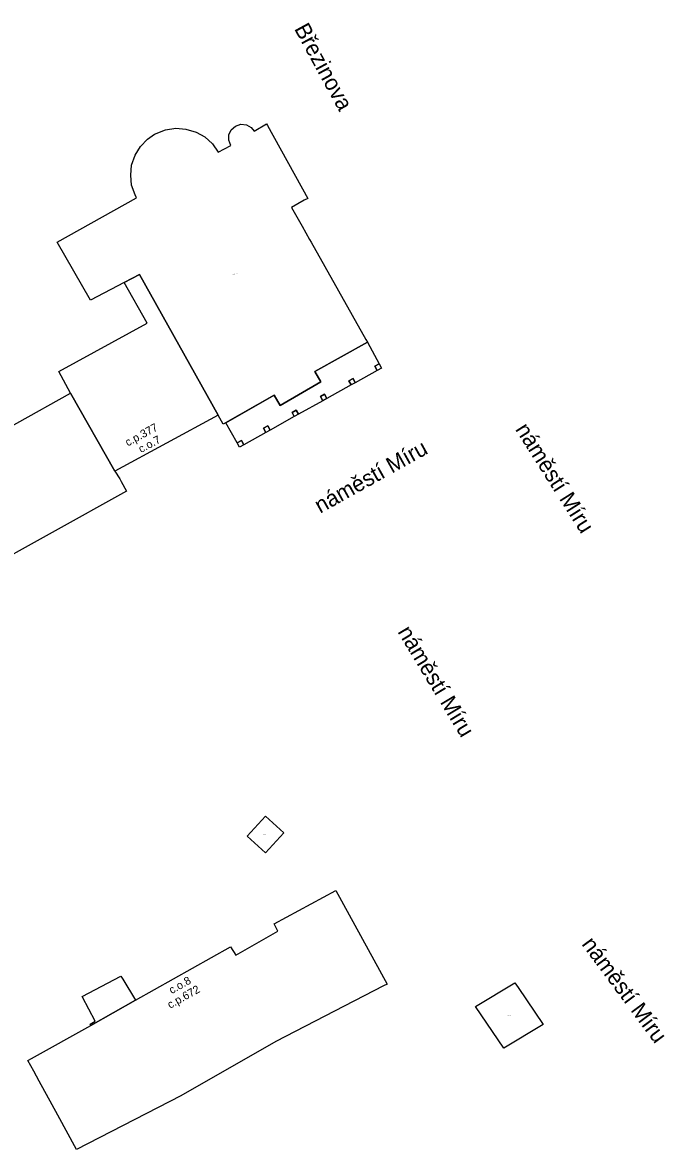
# Model space of a CAD drawing. Extents: x -600391 to -599491, y -1160176 to -1159402.
# Drawn here: x -600035.1 to -599954.9, y -1159820.6 to -1159679.8 of the extents above; entities that cross this region are included whole.
import ezdxf

# ---------------------------------------------------------------- set-up
doc = ezdxf.new("R2010")
doc.units = 0
for name, color, linetype in [('Level 10', 7, 'Continuous'), ('Level 11', 7, 'Continuous'), ('Level 12', 7, 'Continuous'), ('Level 24', 7, 'Continuous'), ('Level 25', 7, 'Continuous'), ('Level 61', 7, 'Continuous'), ('Level 62', 7, 'Continuous')]:
    doc.layers.add(name, color=color, linetype=linetype)

msp = doc.modelspace()

# ---------------------------------------------------------------- linework, layer by layer
at = {"layer": 'Level 61'}
for points in [[(-600018.61, -1159693.77), (-600017.24, -1159693.22)], [(-600017.24, -1159693.22), (-600015.96, -1159693.03)], [(-600015.96, -1159693.03), (-600014.69, -1159693.13)], [(-600014.69, -1159693.13), (-600013.44, -1159693.51)], [(-600013.44, -1159693.51), (-600012.35, -1159694.12)], [(-600009.32, -1159693.84), (-600009.04, -1159693.22)], [(-600009.04, -1159693.22), (-600008.52, -1159692.78)], [(-600008.52, -1159692.78), (-600007.84, -1159692.54)], [(-600007.84, -1159692.54), (-600007.14, -1159692.62)], [(-600007.14, -1159692.62), (-600006.54, -1159692.96)], [(-600006.54, -1159692.96), (-600006.18, -1159693.38)], [(-600006.18, -1159693.38), (-600004.65, -1159692.47)], [(-600004.65, -1159692.47), (-600004.52, -1159692.71)], [(-600004.52, -1159692.71), (-599999.49, -1159701.8)], [(-600020.37, -1159695.31), (-600019.5, -1159694.38)], [(-600019.5, -1159694.38), (-600018.61, -1159693.77)], [(-600012.35, -1159694.12), (-600011.38, -1159695)], [(-600011.38, -1159695), (-600010.66, -1159696.02)], [(-600009.35, -1159694.53), (-600009.32, -1159693.84)], [(-600009.1, -1159695.2), (-600009.35, -1159694.53)], [(-600021.48, -1159697.64), (-600021.05, -1159696.4)], [(-600021.05, -1159696.4), (-600020.37, -1159695.31)], [(-600010.66, -1159696.02), (-600009.1, -1159695.2)], [(-600021.6, -1159698.88), (-600021.48, -1159697.64)], [(-600021.48, -1159700.14), (-600021.6, -1159698.88)], [(-600021.04, -1159701.36), (-600021.48, -1159700.14)], [(-600030.77, -1159707.26), (-600020.86, -1159701.72)], [(-600020.86, -1159701.72), (-600021.04, -1159701.36)], [(-599999.92, -1159702.04), (-600001.52, -1159702.92)], [(-599999.49, -1159701.8), (-599999.92, -1159702.04)], [(-600001.52, -1159702.92), (-600000.19, -1159705.25)], [(-600000.19, -1159705.25), (-599999.27, -1159706.95)], [(-600026.6, -1159714.52), (-600030.77, -1159707.26)], [(-599999.27, -1159706.95), (-599999.05, -1159707.28)], [(-599999.05, -1159707.28), (-599992.21, -1159719.41)], [(-600020.51, -1159711.3), (-600022.4, -1159712.29)], [(-600022.4, -1159712.29), (-600020.51, -1159711.3)], [(-600010.67, -1159728.89), (-600020.51, -1159711.3)], [(-600020.51, -1159711.3), (-600010.67, -1159728.89)], [(-600022.4, -1159712.29), (-600026.6, -1159714.52)], [(-600019.53, -1159717.38), (-600022.4, -1159712.29)], [(-600030.58, -1159723.41), (-600019.53, -1159717.38)], [(-599998.6, -1159723.43), (-599992, -1159719.77)], [(-599992, -1159719.77), (-599998.6, -1159723.43)], [(-599992.21, -1159719.41), (-599992, -1159719.77)], [(-599992, -1159719.77), (-599990.56, -1159722.46)], [(-599991.1, -1159722.76), (-599990.56, -1159722.46)], [(-599990.56, -1159722.46), (-599991.1, -1159722.76)], [(-599990.8, -1159723.28), (-599991.1, -1159722.76)], [(-599991.1, -1159722.76), (-599990.8, -1159723.28)], [(-599990.28, -1159722.99), (-599990.8, -1159723.28)], [(-599990.56, -1159722.46), (-599990.28, -1159722.99)], [(-600029.11, -1159726.12), (-600030.58, -1159723.41)], [(-599997.85, -1159724.73), (-599998.6, -1159723.43)], [(-599998.6, -1159723.43), (-599997.85, -1159724.73)], [(-599994.36, -1159724.58), (-599993.83, -1159724.28)], [(-599993.83, -1159724.28), (-599994.36, -1159724.58)], [(-599994.07, -1159725.1), (-599994.36, -1159724.58)], [(-599994.36, -1159724.58), (-599994.07, -1159725.1)], [(-599993.83, -1159724.28), (-599993.54, -1159724.82)], [(-599993.54, -1159724.82), (-599993.83, -1159724.28)], [(-599990.8, -1159723.28), (-599993.54, -1159724.82)], [(-600002.93, -1159727.66), (-599997.85, -1159724.73)], [(-599997.85, -1159724.73), (-600002.93, -1159727.66)], [(-599994.07, -1159725.1), (-599997.08, -1159726.8)], [(-599993.54, -1159724.82), (-599994.07, -1159725.1)], [(-600035.83, -1159729.89), (-600029.11, -1159726.12)], [(-600023.56, -1159735.86), (-600029.11, -1159726.12)], [(-600029.11, -1159726.12), (-600023.56, -1159735.86)], [(-600003.68, -1159726.39), (-600010.03, -1159730)], [(-600009.73, -1159729.83), (-600003.68, -1159726.39)], [(-600003.68, -1159726.39), (-600002.93, -1159727.66)], [(-600002.93, -1159727.66), (-600003.68, -1159726.39)], [(-599997.61, -1159727.08), (-600000.63, -1159728.77)], [(-599997.9, -1159726.55), (-599997.38, -1159726.26)], [(-599997.38, -1159726.26), (-599997.9, -1159726.55)], [(-599997.61, -1159727.08), (-599997.9, -1159726.55)], [(-599997.9, -1159726.55), (-599997.61, -1159727.08)], [(-599997.08, -1159726.8), (-599997.61, -1159727.08)], [(-599997.38, -1159726.26), (-599997.08, -1159726.8)], [(-599997.08, -1159726.8), (-599997.38, -1159726.26)], [(-600001.45, -1159728.53), (-600000.93, -1159728.24)], [(-600000.93, -1159728.24), (-600001.45, -1159728.53)], [(-600001.16, -1159729.05), (-600001.45, -1159728.53)], [(-600001.45, -1159728.53), (-600001.16, -1159729.05)], [(-600000.63, -1159728.77), (-600001.16, -1159729.05)], [(-600000.93, -1159728.24), (-600000.63, -1159728.77)], [(-600000.63, -1159728.77), (-600000.93, -1159728.24)], [(-600010.67, -1159728.89), (-600023.56, -1159735.86)], [(-600010.03, -1159730), (-600010.67, -1159728.89)], [(-600008.28, -1159732.34), (-600009.73, -1159729.83)], [(-600005, -1159730.51), (-600004.47, -1159730.21)], [(-600004.47, -1159730.21), (-600005, -1159730.51)], [(-600004.47, -1159730.21), (-600004.17, -1159730.75)], [(-600004.17, -1159730.75), (-600004.47, -1159730.21)], [(-600001.16, -1159729.05), (-600004.17, -1159730.75)], [(-600004.71, -1159731.03), (-600007.46, -1159732.58)], [(-600004.71, -1159731.03), (-600005, -1159730.51)], [(-600005, -1159730.51), (-600004.71, -1159731.03)], [(-600004.17, -1159730.75), (-600004.71, -1159731.03)], [(-600008.28, -1159732.34), (-600007.76, -1159732.04)], [(-600007.76, -1159732.04), (-600008.28, -1159732.34)], [(-600007.99, -1159732.86), (-600008.28, -1159732.34)], [(-600007.46, -1159732.58), (-600007.99, -1159732.86)], [(-600007.76, -1159732.04), (-600007.46, -1159732.58)], [(-600007.46, -1159732.58), (-600007.76, -1159732.04)], [(-600023.56, -1159735.86), (-600022.96, -1159736.85)], [(-600022.96, -1159736.85), (-600022.79, -1159737.15)], [(-600022.79, -1159737.15), (-600022.11, -1159738.38)], [(-600022.11, -1159738.38), (-600040.75, -1159748.71)], [(-600007.05, -1159781.48), (-600004.78, -1159778.98)], [(-600004.78, -1159778.98), (-600002.49, -1159781.04)], [(-600004.76, -1159783.54), (-600007.05, -1159781.48)], [(-600002.49, -1159781.04), (-600004.76, -1159783.54)], [(-600003.69, -1159792.44), (-599995.99, -1159788.26)], [(-599995.99, -1159788.26), (-599989.55, -1159799.94)], [(-600008.47, -1159796.34), (-600003.23, -1159793.33)], [(-600003.23, -1159793.33), (-600003.69, -1159792.44)], [(-600020.99, -1159801.96), (-600009.14, -1159795.29)], [(-600009.14, -1159795.29), (-600008.47, -1159796.34)], [(-600027.66, -1159801.51), (-600022.81, -1159798.97)], [(-600022.81, -1159798.97), (-600022.59, -1159799.32)], [(-600022.59, -1159799.32), (-600020.99, -1159801.96)], [(-599990.01, -1159800.18), (-600003.47, -1159807.14)], [(-599989.55, -1159799.94), (-599990.01, -1159800.18)], [(-599978.52, -1159802.75), (-599973.61, -1159799.78)], [(-599973.61, -1159799.78), (-599973.2, -1159800.38)], [(-599973.2, -1159800.38), (-599970.07, -1159805)], [(-600027.61, -1159801.6), (-600027.66, -1159801.51)], [(-600026.03, -1159804.58), (-600027.61, -1159801.6)], [(-600026.56, -1159805.11), (-600020.99, -1159801.96)], [(-600020.99, -1159801.96), (-600026.56, -1159805.11)], [(-599975, -1159807.96), (-599978.52, -1159802.75)], [(-600026.66, -1159804.94), (-600026.03, -1159804.58)], [(-600033.98, -1159809.23), (-600026.56, -1159805.11)], [(-600026.56, -1159805.11), (-600026.66, -1159804.94)], [(-599970.07, -1159805), (-599975, -1159807.96)], [(-600003.47, -1159807.14), (-600015.35, -1159813.93)], [(-600034.43, -1159809.48), (-600033.98, -1159809.23)], [(-600033.7, -1159810.82), (-600034.43, -1159809.48)], [(-600033.01, -1159812.09), (-600033.7, -1159810.82)], [(-600031.42, -1159815.02), (-600033.01, -1159812.09)], [(-600015.35, -1159813.93), (-600028.35, -1159820.61)], [(-600030.71, -1159816.31), (-600031.42, -1159815.02)], [(-600028.35, -1159820.61), (-600030.71, -1159816.31)]]:
    msp.add_lwpolyline(points, dxfattribs=at)
at = {"layer": 'Level 62'}
for points in [[(-599999.27, -1159706.95), (-599999.05, -1159707.28), (-599992.21, -1159719.41), (-599992, -1159719.77), (-599998.6, -1159723.43), (-599997.85, -1159724.73), (-600002.93, -1159727.66), (-600003.68, -1159726.39), (-600010.03, -1159730), (-600010.67, -1159728.89), (-600020.51, -1159711.3), (-600022.4, -1159712.29), (-600026.6, -1159714.52), (-600030.77, -1159707.26), (-600020.86, -1159701.72), (-600021.04, -1159701.36), (-600021.48, -1159700.14), (-600021.6, -1159698.88), (-600021.48, -1159697.64), (-600021.05, -1159696.4), (-600020.37, -1159695.31), (-600019.5, -1159694.38), (-600018.61, -1159693.77), (-600017.24, -1159693.22), (-600015.96, -1159693.03), (-600014.69, -1159693.13), (-600013.44, -1159693.51), (-600012.35, -1159694.12), (-600011.38, -1159695), (-600010.66, -1159696.02), (-600009.1, -1159695.2), (-600009.35, -1159694.53), (-600009.32, -1159693.84), (-600009.04, -1159693.22), (-600008.52, -1159692.78), (-600007.84, -1159692.54), (-600007.14, -1159692.62), (-600006.54, -1159692.96), (-600006.18, -1159693.38), (-600004.65, -1159692.47), (-600004.52, -1159692.71), (-599999.49, -1159701.8), (-599999.92, -1159702.04), (-600001.52, -1159702.92), (-600000.19, -1159705.25), (-599999.27, -1159706.95)], [(-600029.11, -1159726.12), (-600030.58, -1159723.41), (-600019.53, -1159717.38), (-600022.4, -1159712.29), (-600020.51, -1159711.3), (-600010.67, -1159728.89), (-600023.56, -1159735.86), (-600029.11, -1159726.12)], [(-600007.46, -1159732.58), (-600007.76, -1159732.04), (-600008.28, -1159732.34), (-600009.73, -1159729.83), (-600003.68, -1159726.39), (-600002.93, -1159727.66), (-599997.85, -1159724.73), (-599998.6, -1159723.43), (-599992, -1159719.77), (-599990.56, -1159722.46), (-599991.1, -1159722.76), (-599990.8, -1159723.28), (-599993.54, -1159724.82), (-599993.83, -1159724.28), (-599994.36, -1159724.58), (-599994.07, -1159725.1), (-599997.08, -1159726.8), (-599997.38, -1159726.26), (-599997.9, -1159726.55), (-599997.61, -1159727.08), (-600000.63, -1159728.77), (-600000.93, -1159728.24), (-600001.45, -1159728.53), (-600001.16, -1159729.05), (-600004.17, -1159730.75), (-600004.47, -1159730.21), (-600005, -1159730.51), (-600004.71, -1159731.03), (-600007.46, -1159732.58)], [(-599990.56, -1159722.46), (-599990.28, -1159722.99), (-599990.8, -1159723.28), (-599991.1, -1159722.76), (-599990.56, -1159722.46)], [(-599994.07, -1159725.1), (-599994.36, -1159724.58), (-599993.83, -1159724.28), (-599993.54, -1159724.82), (-599994.07, -1159725.1)], [(-600029.11, -1159726.12), (-600023.56, -1159735.86), (-600022.96, -1159736.85), (-600022.79, -1159737.15), (-600022.11, -1159738.38), (-600040.75, -1159748.71), (-600041.39, -1159749.06), (-600044.45, -1159750.75), (-600045.04, -1159751.07), (-600045.74, -1159751.46), (-600063.64, -1159761.34), (-600070.35, -1159749.14), (-600052.61, -1159739.29), (-600051.53, -1159738.69), (-600047.82, -1159736.59), (-600042.29, -1159733.51), (-600037.91, -1159731.05), (-600035.83, -1159729.89), (-600029.11, -1159726.12)], [(-599997.08, -1159726.8), (-599997.61, -1159727.08), (-599997.9, -1159726.55), (-599997.38, -1159726.26), (-599997.08, -1159726.8)], [(-600001.16, -1159729.05), (-600001.45, -1159728.53), (-600000.93, -1159728.24), (-600000.63, -1159728.77), (-600001.16, -1159729.05)], [(-600004.17, -1159730.75), (-600004.71, -1159731.03), (-600005, -1159730.51), (-600004.47, -1159730.21), (-600004.17, -1159730.75)], [(-600007.46, -1159732.58), (-600007.99, -1159732.86), (-600008.28, -1159732.34), (-600007.76, -1159732.04), (-600007.46, -1159732.58)], [(-600004.76, -1159783.54), (-600007.05, -1159781.48), (-600004.78, -1159778.98), (-600002.49, -1159781.04), (-600004.76, -1159783.54)], [(-599990.01, -1159800.18), (-600003.47, -1159807.14), (-600015.35, -1159813.93), (-600028.35, -1159820.61), (-600030.71, -1159816.31), (-600031.42, -1159815.02), (-600033.01, -1159812.09), (-600033.7, -1159810.82), (-600034.43, -1159809.48), (-600033.98, -1159809.23), (-600026.56, -1159805.11), (-600020.99, -1159801.96), (-600009.14, -1159795.29), (-600008.47, -1159796.34), (-600003.23, -1159793.33), (-600003.69, -1159792.44), (-599995.99, -1159788.26), (-599989.55, -1159799.94), (-599990.01, -1159800.18)], [(-600027.61, -1159801.6), (-600027.66, -1159801.51), (-600022.81, -1159798.97), (-600022.59, -1159799.32), (-600020.99, -1159801.96), (-600026.56, -1159805.11), (-600026.66, -1159804.94), (-600026.03, -1159804.58), (-600027.61, -1159801.6)], [(-599978.52, -1159802.75), (-599973.61, -1159799.78), (-599973.2, -1159800.38), (-599970.07, -1159805), (-599975, -1159807.96), (-599978.52, -1159802.75)]]:
    msp.add_lwpolyline(points, dxfattribs=at)

# ---------------------------------------------------------------- texts
at = {"layer": 'Level 10'}
for s, rotation, p in [('c.o.7', 28.4001, (-600020.3, -1159733.62)), ('c.o.8', 29.3746, (-600016.48, -1159801.22))]:
    msp.add_text(s, height=1, rotation=rotation, dxfattribs=at).set_placement(p)
at = {"layer": 'Level 11'}
for s, rotation, p in [('Březinova', 298.6405, (-600001.22, -1159680.6)), ('náměstí Míru', 302.3331, (-599973.62, -1159730.64)), ('náměstí Míru', 29.1526, (-599997.94, -1159741.2)), ('náměstí Míru', 301.0554, (-599988.31, -1159755.93)), ('náměstí Míru', 306.5061, (-599965.34, -1159794.97))]:
    msp.add_text(s, height=2, rotation=rotation, dxfattribs=at).set_placement(p)
at = {"layer": 'Level 12'}
for s, rotation, p in [('c.p.377', 28.4001, (-600021.96, -1159732.8)), ('c.p.672', 29.3746, (-600016.67, -1159803.05))]:
    msp.add_text(s, height=1, rotation=rotation, dxfattribs=at).set_placement(p)
at = {"layer": 'Level 24'}
for s, p in [('c.z.105', (-600005.1, -1159781.33)), ('c.z.200', (-599974.53, -1159803.88))]:
    msp.add_text(s, height=0.1, dxfattribs=at).set_placement(p)
at = {"layer": 'Level 25'}
msp.add_text('c.pp.377_A', height=0.1, dxfattribs=at).set_placement((-600008.94, -1159711.31))

doc.saveas('drawing.dxf')
